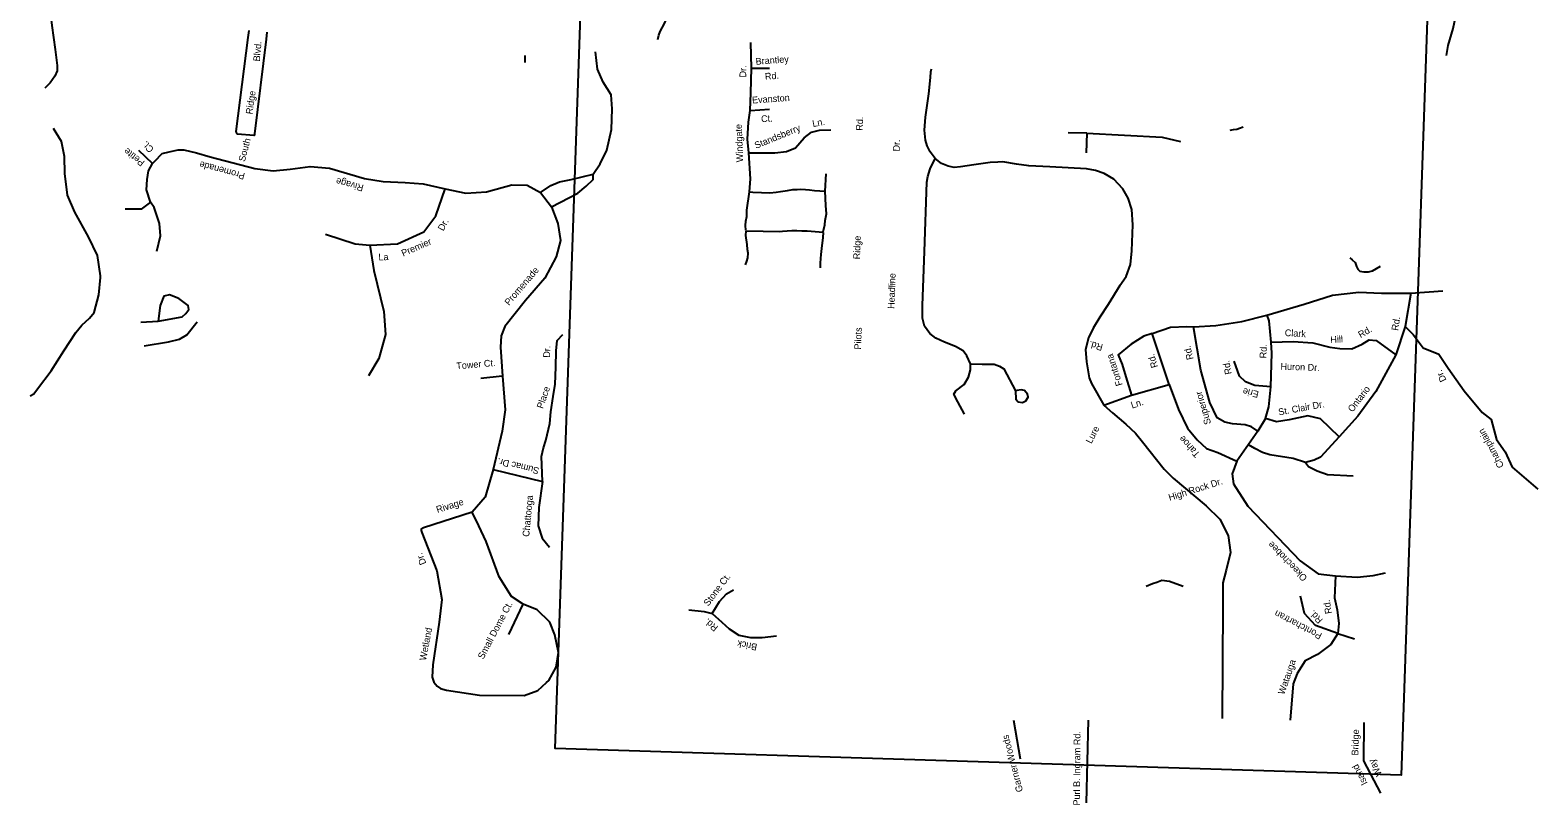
# Model space of a CAD drawing. Extents: x 2308163 to 2335412, y -96774 to 125428.
# Drawn here: x 2314476 to 2321788, y -50957 to -47201 of the extents above; entities that cross this region are included whole.
import ezdxf

# ---------------------------------------------------------------- set-up
doc = ezdxf.new("R2010")
doc.units = 0
for name, color, linetype in [('Old_Level_10', 7, 'Continuous'), ('Old_Level_35', 7, 'Continuous'), ('Old_Level_63', 7, 'Continuous')]:
    doc.layers.add(name, color=color, linetype=linetype)

msp = doc.modelspace()

# ---------------------------------------------------------------- linework, layer by layer
at = {"layer": 'Old_Level_35'}
for p, q in [((2315533.7, -47236.9), (2315537.9, -47203.3)), ((2315624.6, -47211.8), (2315620.5, -47245.4)), ((2316877.4, -47357.9), (2316876.3, -47324.1)), ((2318331.2, -47981.2), (2318337.2, -47897.9))]:
    msp.add_line(p, q, dxfattribs=at)
for points in [[(2317520.9, -47246.1), (2317524.5, -47226.1), (2317531.2, -47208.1), (2317552.2, -47169.5), (2317578.5, -47108.4), (2317616.7, -47011.4), (2317651.9, -46911.3), (2317708, -46775.6)], [(2314565.6, -47054.4), (2314567.5, -47070.4), (2314581, -47178.2), (2314597.6, -47295.2), (2314607, -47373.1), (2314606.2, -47399.1), (2314596.3, -47424.1), (2314572.5, -47457.2), (2314547.6, -47482.4)], [(2321345.9, -47324.2), (2321353.3, -47275.4), (2321376.9, -47193.1), (2321390.3, -47131.3), (2321393.3, -47101.2)], [(2315620.5, -47245.4), (2315564.7, -47704.4), (2315564.4, -47708.7), (2315563.9, -47710.3), (2315563.2, -47711.5), (2315562.1, -47712), (2315560.4, -47712.3), (2315482.4, -47705.5), (2315479.4, -47703.7), (2315477.9, -47701.4), (2315476.7, -47698.5), (2315476.2, -47696), (2315475.9, -47692.6), (2315533.7, -47236.9)], [(2317005.2, -48057.7), (2317132.5, -47991.2), (2317172.5, -47957), (2317205.9, -47925.9), (2317206.8, -47900.1), (2317240.8, -47849.6), (2317272.2, -47782.9), (2317295, -47683.5), (2317298.5, -47583.6), (2317294.3, -47515.6), (2317254.5, -47452.9), (2317227.6, -47390.6), (2317218.5, -47306.6)], [(2317965.2, -47985.9), (2317970.2, -47921.9), (2317961.3, -47795.6), (2317955.6, -47729.2), (2317960, -47647.1), (2317968.4, -47590.8), (2317971.4, -47505.4), (2317973.9, -47386), (2317971.1, -47260.8)], [(2317973.9, -47386), (2318061.1, -47385.8)], [(2318864.9, -47823.9), (2318840.8, -47790.9), (2318827.3, -47762), (2318818.4, -47734.4), (2318813.2, -47686.8), (2318818.7, -47623.1), (2318834.8, -47510.5), (2318842.8, -47430.7), (2318845.1, -47404), (2318846.9, -47389.2)], [(2317968.4, -47590.8), (2318062.3, -47584.4)], [(2320296.2, -47686.5), (2320312.9, -47683.4), (2320328.2, -47680.9), (2320341.8, -47676.5), (2320359.2, -47669.8)], [(2314817.3, -48392.4), (2314803.4, -48293), (2314759, -48203.8), (2314692.1, -48083), (2314656.9, -48001.2), (2314644, -47896.5), (2314642.1, -47813.4), (2314627.9, -47741.9), (2314589.8, -47678.9)], [(2317961.3, -47795.6), (2318088, -47796.8), (2318143.5, -47789.2), (2318188.2, -47772), (2318230.3, -47723.4), (2318264.9, -47695.7), (2318304.7, -47686.1), (2318359.4, -47685)], [(2319601, -47701.2), (2319510.6, -47699.3)], [(2319601, -47701.2), (2319596.9, -47796.3)], [(2319601, -47701.2), (2319967, -47720.5), (2320055.5, -47741.9)], [(2315070.1, -47848.1), (2315003.6, -47784.2)], [(2315058.9, -48034.9), (2315039.7, -47975), (2315043.7, -47925.4), (2315050, -47883), (2315070.1, -47848.1), (2315080, -47836.6), (2315116.8, -47800), (2315150.3, -47791.6), (2315193.4, -47781.3), (2315221.8, -47782.3), (2315283, -47796.2), (2315348.7, -47815.1)], [(2315348.7, -47815.1), (2315566, -47872.2), (2315654.3, -47883.1), (2315737.3, -47876.1), (2315834.3, -47861.8), (2315928.5, -47870.9), (2316098.2, -47920.1), (2316187.9, -47935), (2316294.1, -47940.6), (2316382.6, -47945.6), (2316488.1, -47970.9), (2316589.8, -47992.2), (2316688.5, -47985.7), (2316811.9, -47950.6), (2316886.7, -47953.2), (2316950.5, -47988.9), (2317005.2, -48057.7), (2317035.9, -48139.4), (2317048.8, -48220.6), (2317026.4, -48300.6), (2316971.6, -48403), (2316879.2, -48512), (2316778.3, -48638.5), (2316761, -48683.2), (2316757.2, -48738.2), (2316766.1, -48878.2), (2316780.2, -49042.1), (2316764.8, -49145.9), (2316720.9, -49331.4), (2316682.8, -49466), (2316619.2, -49538.6), (2316384.2, -49613.2), (2316372.1, -49620.6), (2316371.9, -49626.5), (2316375.5, -49636.5), (2316447.9, -49822.1), (2316472.7, -49960.7), (2316459, -50070.5), (2316428.2, -50278.1), (2316426.2, -50337.1), (2316433.2, -50362.9), (2316450.3, -50381.2), (2316465.6, -50393.6), (2316494.9, -50400.5), (2316655.6, -50425.7), (2316872.3, -50427.3), (2316938.2, -50402), (2316980.8, -50364.1), (2316991, -50354.6), (2317026.8, -50288.9), (2317039, -50218.5), (2317020.3, -50133.2), (2316996.8, -50071.3), (2316935.8, -50012.1), (2316867.8, -49984.2), (2316810, -49946.8), (2316750.3, -49852.2), (2316687.2, -49680.7), (2316652.4, -49604.7), (2316619.2, -49538.6)], [(2319035.9, -48818.2), (2319019.1, -48779.5), (2319001.6, -48756.1), (2318963.2, -48734.7), (2318909.9, -48714.6), (2318868, -48694.5), (2318839.2, -48671.7), (2318814.2, -48636.9), (2318803.4, -48598.3), (2318803.8, -48536.5), (2318813.7, -48274.1), (2318825.3, -47939.1), (2318829.7, -47911.4), (2318840.6, -47873.5), (2318864.9, -47823.9)], [(2319761.1, -48439.9), (2319791.5, -48395.8), (2319812.4, -48337.5), (2319818.4, -48271.2), (2319824, -48145.9), (2319819.1, -48070.4), (2319802.1, -48015.9), (2319776.1, -47971), (2319731.3, -47923.1), (2319685.7, -47896.4), (2319642.3, -47881.1), (2319598.6, -47873.3), (2319421.9, -47863.4), (2319320.4, -47858.7), (2319260.4, -47850.3), (2319194.2, -47840.5), (2319169.8, -47840.8), (2319132, -47843.4), (2319052.2, -47853.7), (2318988.1, -47864.5), (2318956.8, -47867.3), (2318928.4, -47861.1), (2318896.3, -47848.3), (2318864.9, -47823.9)], [(2316950.5, -47988.9), (2317001.3, -47954.3), (2317043.9, -47936.4), (2317099.2, -47925.4), (2317206.8, -47900.1)], [(2315091, -48273), (2315107.9, -48197.8), (2315102.8, -48138.4), (2315077, -48061.6), (2315058.9, -48034.9), (2315015.1, -48069), (2314936.8, -48068.7)], [(2315908.5, -48189.6), (2316052.6, -48237.8), (2316123.3, -48244.2), (2316257.5, -48237), (2316385.6, -48178.4), (2316443.4, -48101.7), (2316488.1, -47970.9)], [(2317947.8, -48171.2), (2317946.2, -48149.1), (2317946.9, -48127.1), (2317951.7, -48104.4), (2317951.1, -48073.7), (2317965.2, -47985.9)], [(2317965.2, -47985.9), (2317981.7, -47986.5), (2318022.7, -47988.7), (2318063.6, -47990.1), (2318093.7, -47987.2), (2318115.8, -47984), (2318149.2, -47978.1), (2318175.3, -47974.3), (2318195.8, -47974.2), (2318212.4, -47972.4), (2318236.8, -47974), (2318255.7, -47975.5), (2318280, -47978.7), (2318331.2, -47981.2)], [(2318322.7, -48179.4), (2318331, -48145.1), (2318331.7, -48124.6), (2318337.6, -48091.7), (2318335.8, -48051.5), (2318331.2, -47981.2)], [(2317944.8, -48339.1), (2317952.1, -48321), (2317956.6, -48305.4), (2317958.9, -48281.9), (2317954.8, -48264.4), (2317953.3, -48239.9), (2317947.7, -48197.2), (2317949.2, -48174.4)], [(2317950.8, -48173.7), (2318112.3, -48176.9), (2318124.2, -48175.7), (2318170.8, -48172.6), (2318194.5, -48172.6), (2318218.9, -48174.3), (2318244.1, -48174.3), (2318322.7, -48180.2)], [(2318308.6, -48353.8), (2318309.4, -48331.1), (2318310.2, -48308.3), (2318311.9, -48289.3), (2318316, -48260.3), (2318322.6, -48206.2), (2318324.2, -48181.8)], [(2316123.3, -48244.2), (2316142.7, -48366.9), (2316191, -48565.5), (2316199, -48676), (2316167.4, -48793), (2316117.2, -48877.9)], [(2320876.9, -48305.9), (2320887, -48314.5), (2320901.8, -48328.5), (2320909.1, -48347.1), (2320914.8, -48360.7), (2320924.8, -48369.6), (2320943.7, -48373.3), (2320966.3, -48373.5), (2320986.6, -48367.5), (2321024.7, -48346.2)], [(2314476, -48973.6), (2314494, -48964), (2314511.9, -48939.8), (2314577.4, -48852.6), (2314638.9, -48755.4), (2314697.5, -48667), (2314726.3, -48632), (2314764, -48596.9), (2314785.9, -48569.7), (2314809.5, -48484.6), (2314817.2, -48400.6), (2314817.3, -48392.4)], [(2319761.1, -48439.9), (2319704, -48532.1), (2319664.2, -48592.2), (2319632.2, -48646.4), (2319608.9, -48693.4), (2319595, -48749.1), (2319598.9, -48809.5), (2319612.3, -48886.3), (2319623.4, -48914.8), (2319683.6, -49019.7), (2319725, -49057), (2319789.5, -49111.4), (2319836.2, -49155.2), (2319871, -49196.6), (2319975.3, -49329.1), (2320019, -49373.2), (2320180.2, -49506.8), (2320245.7, -49571.8), (2320285.7, -49651), (2320297.9, -49734.3), (2320277.4, -49818.9), (2320260.2, -49881.1), (2320261.3, -49994.1), (2320257.1, -50537.7)], [(2319917.2, -48671.8), (2320006.5, -48641.9), (2320086.3, -48637.5), (2320117.8, -48639.6), (2320227.3, -48633.2), (2320352.7, -48613), (2320473.2, -48583.5), (2320654.2, -48530.1), (2320792.8, -48485.4), (2320920.5, -48471.9), (2321029.6, -48475.9), (2321172.6, -48477.2)], [(2321172.6, -48477.2), (2321145, -48637.5), (2321099.6, -48775.8), (2321002.2, -48953.7), (2320914.5, -49072.2), (2320824.1, -49173.1), (2320734.1, -49270.7), (2320704.2, -49286.5), (2320661.3, -49297.5), (2320601.6, -49278.1), (2320488.9, -49260.6), (2320452.8, -49249.5), (2320416.4, -49229.8), (2320384.2, -49211.4)], [(2321172.6, -48477.2), (2321327, -48465.7)], [(2315012.3, -48616.8), (2315096.9, -48612.1), (2315213.2, -48590.5), (2315231, -48575.5), (2315245.5, -48555.8), (2315242.8, -48535.4), (2315196.6, -48502.8), (2315152, -48483.7), (2315124.8, -48491.3), (2315106.6, -48535.7)], [(2315106.6, -48535.7), (2315096.9, -48612.1)], [(2315028.8, -48731.7), (2315147.6, -48711.6), (2315200.8, -48699.4), (2315236, -48678), (2315286.5, -48615.4)], [(2320495.3, -48714.5), (2320484.8, -48611.1), (2320475.8, -48582.8)], [(2316960.1, -49389.4), (2316956.2, -49268.2), (2316965.8, -49225.5), (2316977.7, -49190.9), (2316996.8, -49108.1), (2317001.4, -49051.8), (2317012.1, -48976.8), (2317022.2, -48918), (2317025, -48834.7), (2317027.7, -48756.7), (2317032.2, -48705.7), (2317060.1, -48677.1)], [(2320000.8, -48918.9), (2319917.2, -48671.8), (2319877, -48684.9), (2319816.7, -48723), (2319753.4, -48774.8), (2319771.8, -48821.9), (2319789.8, -48882.7), (2319816.9, -48971.5)], [(2320430.8, -49145.6), (2320398.9, -49123.8), (2320369, -49113.9), (2320306.8, -49109.8), (2320270, -49102), (2320233.8, -49080.1), (2320196.9, -49005.9), (2320154.6, -48850.4), (2320117.8, -48639.6)], [(2321145, -48637.5), (2321183.3, -48677), (2321232.4, -48741), (2321308.4, -48772.9), (2321353.7, -48840.5), (2321430.7, -48949.4), (2321518.7, -49055.1), (2321561.6, -49089.6), (2321587.6, -49185.8), (2321629.5, -49245.9), (2321663.6, -49320.4), (2321788.3, -49427.3)], [(2320824.1, -49173.1), (2320733.4, -49085.2), (2320673.5, -49071.5), (2320581.7, -49090), (2320520.2, -49099.8), (2320468.1, -49084.2), (2320484.3, -49028.1), (2320492.8, -48930.9), (2320498.9, -48766.8), (2320495.3, -48714.5)], [(2320495.3, -48714.5), (2320601.3, -48710.9), (2320697.7, -48716.4), (2320779.4, -48738.7), (2320828.1, -48744.7), (2320885.6, -48745.6), (2320936.3, -48723.5), (2320969.6, -48703), (2321004.3, -48705.2), (2321099.6, -48775.8)], [(2319007.3, -49062.3), (2318975.2, -49003), (2318956.4, -48966.2), (2318965, -48950.4), (2319006.2, -48919.7), (2319027.5, -48884.2), (2319036.8, -48848.4), (2319035.9, -48818.2)], [(2319035.9, -48818.2), (2319093.8, -48820), (2319151, -48821.3), (2319176.6, -48829.7), (2319197.9, -48843.3), (2319254.3, -48950.1), (2319256.4, -48990.2), (2319267.5, -49002.7), (2319288.4, -49006.7), (2319305.8, -48998), (2319316.8, -48981), (2319313, -48965.2), (2319297.9, -48948.1), (2319282.4, -48945), (2319262.2, -48947.8), (2319254.3, -48950.1)], [(2320492.8, -48930.9), (2320415.9, -48924.2), (2320370.6, -48905.8), (2320341.9, -48878.2), (2320315.8, -48806.4)], [(2316662.4, -48887.8), (2316766, -48876.6)], [(2319816.9, -48971.5), (2320000.8, -48918.9)], [(2320000.8, -48918.9), (2320045.3, -49040.9), (2320089.9, -49130.5), (2320135.7, -49187), (2320181.9, -49228.9), (2320236.2, -49249.1), (2320327.8, -49291.2)], [(2319683.6, -49019.7), (2319816.9, -48971.5)], [(2320468.1, -49084.2), (2320430.8, -49145.6), (2320327.8, -49291.2), (2320306, -49352.7), (2320311.7, -49400.6), (2320381.3, -49509.3), (2320636.3, -49774.7), (2320722.2, -49836.3), (2320806.2, -49846.5), (2320912.3, -49853.8), (2320989.7, -49845.5), (2321048.8, -49832.9)], [(2316720.9, -49331.4), (2316960.1, -49389.4), (2316942.3, -49515.3), (2316939.3, -49603.9), (2316958.7, -49663.8), (2316994.9, -49708.1)], [(2320661.3, -49297.5), (2320675.9, -49316), (2320717.7, -49337.6), (2320768.8, -49355.7), (2320892.6, -49362)], [(2319888.1, -49896.8), (2319919.7, -49883.2), (2319940.6, -49876.7), (2319964.7, -49868.2), (2320002, -49873.1), (2320067.8, -49896)], [(2320806.2, -49846.5), (2320802.5, -49952.7), (2320815.2, -50011.8), (2320823.9, -50078), (2320818.6, -50125.5), (2320783.7, -50179.3), (2320719.7, -50228.4), (2320659.9, -50259.3), (2320621.1, -50320.3), (2320601, -50370.9), (2320587.5, -50546.7)], [(2317783.5, -50029), (2317819, -49971), (2317853.8, -49933.6), (2317888, -49914.1)], [(2316797.2, -50131.8), (2316867.8, -49984.2)], [(2317670.7, -50012.2), (2317745.2, -50019.9), (2317783.5, -50029), (2317831, -50071.8), (2317866, -50103.9), (2317913.9, -50133.9), (2317970.1, -50146.1), (2318026.8, -50145.5), (2318096, -50136.9)], [(2320818.6, -50125.5), (2320709.9, -50086.6), (2320656.8, -50029.8), (2320637.7, -49944.8)], [(2320818.6, -50125.5), (2320898.4, -50151.7)], [(2319279.7, -50735.2), (2319246.2, -50547.9)], [(2319598.8, -50947.8), (2319608.6, -50545.6)], [(2321026.6, -50900.3), (2320944, -50743.5), (2320946.5, -50558.4)]]:
    msp.add_lwpolyline(points, dxfattribs=at)
at = {"layer": 'Old_Level_63'}
msp.add_lwpolyline([(2321352.1, -44241.4), (2321125.4, -50813.5), (2317022.8, -50684), (2317287.3, -43015.4)], dxfattribs=at)

# ---------------------------------------------------------------- texts
at = {"layer": 'Old_Level_10'}
for s, height, rotation, p in [('Blvd.', 32.81, 85.2272, (2315590.2, -47354.1)), ('Dr.', 32.81, 89.43848, (2317948.8, -47430.9)), ('Brantley', 32.81, 4.36455, (2317995.8, -47369.6)), ('Rd.', 32.81, 4.36455, (2318040.9, -47442.1)), ('Ridge', 32.81, 81.86228, (2315553.8, -47610.9)), ('Evanston', 32.81, 3.97146, (2317978.3, -47557.1)), ('Windgate', 32.81, 92.22382, (2317934.4, -47841)), ('Standsberry', 32.808, 22.42356, (2317997.1, -47777.3)), ('Ct.', 32.81, 3.97146, (2318022, -47648.2)), ('Ln.', 32.81, 10.83056, (2318272.8, -47671.2)), ('Rd.', 32.81, 87.92984, (2318513.6, -47689.3)), ('Ct.', 32.81, 134.3578, (2315078.4, -47776.4)), ('South ', 32.81, 75.4775, (2315517.3, -47841)), ('Dr.', 32.81, 87.06731, (2318692.8, -47790.1)), ('Petite', 32.81, 141.98233, (2315034.4, -47838.7)), ('Promenade', 32.81, 164.81853, (2315520.3, -47895.1)), ('Rivage ', 32.81, 164.92486, (2316095.8, -47952.5)), ('Dr.', 32.81, 61.57164, (2316479.7, -48177.7)), ('Premier ', 32.81, 23.57301, (2316285, -48299.4)), ('Ridge', 32.81, 88.02472, (2318500.6, -48312.8)), ('La ', 32.81, 2.86284, (2316166, -48318.2)), ('Promenade', 32.81, 49.50563, (2316798.5, -48538.8)), ('Headline', 32.81, 88.02472, (2318667.8, -48552.9)), ('Rd.', 32.81, 80.95616, (2321110.3, -48659.9)), ('Pilots', 32.81, 87.86328, (2318505.6, -48750.1)), ('Clark', 32.81, 356.62688, (2320560.1, -48684.1)), ('Hill', 32.81, 3.13085, (2320782.9, -48718.1)), ('Rd.', 32.81, 29.86027, (2320928.6, -48694.9)), ('Dr.', 32.81, 87.43691, (2316996.5, -48790)), ('Rd.', 32.81, 164.56591, (2319681.5, -48725.2)), ('Fontana', 32.81, 107.79841, (2319774.9, -48920.6)), ('Rd.', 32.81, 106.68375, (2319946.2, -48833.3)), ('Rd.', 32.81, 103.63519, (2320118.5, -48795.2)), ('Rd.', 32.81, 87.8778, (2320471.4, -48792.9)), ('Tower Ct.', 32.81, 4.95381, (2316544.2, -48845.7)), ('Rd.', 32.81, 101.32255, (2320304.2, -48867.1)), ('Huron Dr.', 32.81, 358.02472, (2320539.8, -48847.2)), ('Dr.', 32.81, 116.27225, (2321346.2, -48897.2)), ('Place', 32.81, 71.09145, (2316962.7, -49038.7)), ('Superior', 32.81, 106.40769, (2320204, -49108.1)), ('Erie', 32.81, 167.35059, (2320437.3, -48952.4)), ('Ontario', 32.81, 52.59136, (2320889.6, -49055.8)), ('Ln.', 32.81, 18.50929, (2319820.8, -49036.1)), ('St. Clair Dr.', 32.808, 10.39368, (2320533, -49069.4)), ('Lure', 32.81, 62.52738, (2319622.9, -49208.8)), ('Champlain', 32.81, 118.40322, (2321625.3, -49313.6)), ('Tahoe', 32.81, 132.39471, (2320152.1, -49255.4)), ('Sumac Dr.', 32.81, 166.54323, (2316947.1, -49323.2)), ('High Rock Dr.', 32.808, 17.52093, (2320002.8, -49483.6)), ('Rivage ', 32.81, 17.4763, (2316451.3, -49542.2)), ('Chattooga', 32.81, 84.52435, (2316896.1, -49658.7)), ('Okeechobee', 32.81, 134.28981, (2320672.4, -49854.3)), ('Dr.', 32.81, 112.2366, (2316398.2, -49786)), ('Stone Ct.', 32.81, 52.95387, (2317765.1, -49996.4)), ('Small Dome Ct.', 32.808, 62.20697, (2316673.7, -50253.8)), ('Pontchartran', 32.808, 152.53167, (2320744.4, -50127.7)), ('Rd.', 32.81, 134.45661, (2320747.8, -50059)), ('Rd.', 32.81, 99.38949, (2320789.9, -50028.4)), ('Rd.', 32.81, 140.7679, (2317815.5, -50093.7)), ('Wetland', 32.81, 79.26719, (2316396, -50259.2)), ('Brick', 32.81, 169.09745, (2318004.2, -50177.4)), ('Watauga', 32.81, 70.85287, (2320557.9, -50425)), ('Bridge', 32.81, 88.41707, (2320917.4, -50717.9)), ('Garner Woods', 32.808, 104.4911, (2319291.6, -50890.5)), ('Purl B. Ingram Rd.', 32.808, 89.57339, (2319567.5, -50960.3)), ('Way', 32.81, 117.30098, (2321033.7, -50808.7)), ('Isand', 32.81, 117.30098, (2320963.7, -50851.8))]:
    msp.add_text(s, height=height, rotation=rotation, dxfattribs=at).set_placement(p)

doc.saveas('drawing.dxf')
